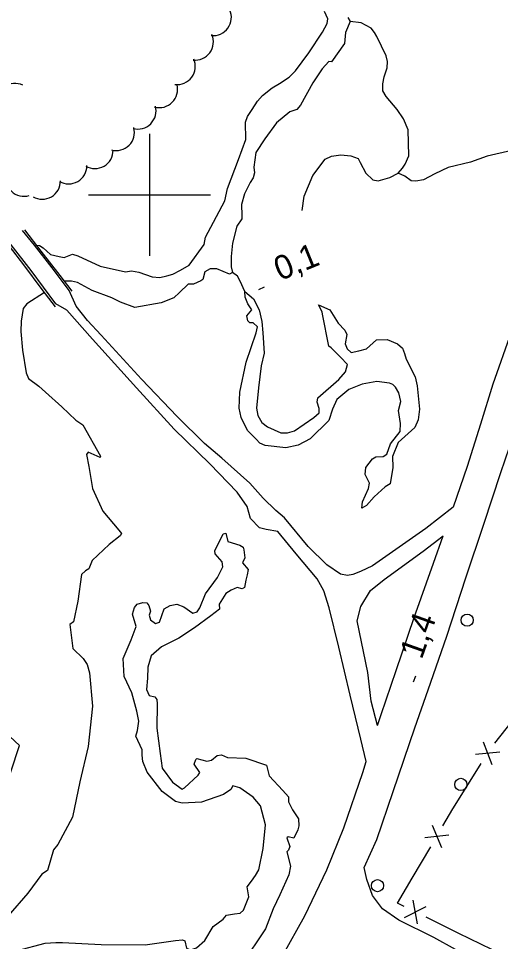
# Model space of a CAD drawing. Extents: x 362852 to 366875, y 5563573 to 5566479.
# Drawn here: x 363178.5 to 363257.7, y 5564877.4 to 5565029 of the extents above; entities that cross this region are included whole.
import ezdxf

# ---------------------------------------------------------------- set-up
doc = ezdxf.new("R2010")
doc.units = 0
for name, color, linetype in [('Niveau 21', 7, 'Continuous'), ('Niveau 26', 7, 'Continuous'), ('Niveau 3', 7, 'Continuous'), ('Niveau 36', 7, 'Continuous'), ('Niveau 37', 7, 'Continuous'), ('Niveau 4', 7, 'Continuous'), ('Niveau 44', 7, 'Continuous'), ('Niveau 61', 7, 'Continuous')]:
    doc.layers.add(name, color=color, linetype=linetype)

msp = doc.modelspace()

# ---------------------------------------------------------------- linework, layer by layer
at = {"layer": 'Niveau 21'}
for points in [[(363372.18, 5565057.69), (363361.37, 5565056.86), (363353.03, 5565055.6), (363345.44, 5565053.87), (363341.3, 5565052.93), (363331.73, 5565049.73), (363323.1, 5565046.35), (363314.99, 5565042.43), (363306.2, 5565037.55), (363298.33, 5565032.24), (363292.69, 5565027.74), (363288.13, 5565023.46), (363282, 5565017.44), (363277.14, 5565011.7), (363273.09, 5565006.11), (363268.51, 5564998.35), (363265.37, 5564991.56), (363261.94, 5564983.91), (363259.38, 5564977.44), (363256.38, 5564968.91), (363254.34, 5564962.36), (363252.17, 5564955.43), (363249.85, 5564948.72)], [(363235.23, 5564889.57), (363237.33, 5564894.18), (363240.03, 5564902.09), (363243.59, 5564912.52), (363245.79, 5564918.73), (363248.83, 5564927.56), (363251.95, 5564937.15), (363254.89, 5564945.97), (363257.71, 5564954.41), (363261.25, 5564964.85), (363262.65, 5564968.94), (363264.15, 5564973.34), (363266.65, 5564980.22), (363269.8, 5564986.99), (363272.24, 5564991.85), (363273.35, 5564994.06), (363277, 5565000.38), (363281.52, 5565006.79), (363283.56, 5565009.38), (363285.33, 5565011.62), (363291.51, 5565018.1), (363296.54, 5565023.16), (363302, 5565027.46), (363308.39, 5565031.6)], [(363249.85, 5564948.72), (363245.4, 5564945.21), (363242.67, 5564943.33), (363236.64, 5564939.13), (363234.66, 5564938.17), (363233.41, 5564937.71), (363232.49, 5564937.51), (363231.39, 5564937.74), (363229.15, 5564939.28), (363226.08, 5564942.3), (363222.15, 5564946.98), (363220.75, 5564948.21), (363218.65, 5564950.22), (363216.45, 5564952.66), (363211.89, 5564956.77), (363209.04, 5564959.17), (363204.56, 5564963.6), (363198.66, 5564969.77), (363192.06, 5564976.98), (363189.8, 5564979.4), (363187.96, 5564981.71), (363186.81, 5564984.28), (363184, 5564988.03), (363181.11, 5564991.77), (363179.16, 5564994.13)], [(363235.59, 5564906.98), (363234.69, 5564910.67), (363232.94, 5564917.89), (363231.1, 5564925.75), (363229.48, 5564932.21), (363228.65, 5564934.98), (363227.52, 5564936.98), (363224.08, 5564941.09), (363221.09, 5564944.75), (363219.16, 5564945.05), (363218.04, 5564945.34), (363216.61, 5564946.89), (363216.04, 5564948.85), (363214.4, 5564951.19), (363209.93, 5564955.84), (363204.06, 5564961.55), (363197.89, 5564968.32), (363190.66, 5564976.31), (363186.41, 5564981.06), (363184.62, 5564982.12), (363180.57, 5564987.58), (363176.88, 5564992.28)], [(363237.45, 5564912.88), (363236.42, 5564916.87), (363235.83, 5564921.58), (363234.11, 5564930.07), (363234.69, 5564932.44), (363236.29, 5564935.06), (363238.56, 5564936.87), (363244.95, 5564941.54), (363248.22, 5564944.04)], [(363237.45, 5564912.88), (363238.03, 5564914.7), (363240.53, 5564921.9), (363243.49, 5564930.63), (363246.64, 5564939.54), (363248.22, 5564944.04)], [(363178.37, 5564814.36), (363183.2, 5564821.26), (363185.41, 5564824.38), (363186.33, 5564825.68), (363188.95, 5564829.38), (363194.29, 5564836.07), (363200.53, 5564844.25), (363207.75, 5564854.22), (363212.87, 5564861.49), (363218.52, 5564869.7), (363221.84, 5564875.11), (363225.53, 5564881.64), (363229.14, 5564889.18), (363231.93, 5564896.12), (363235.02, 5564905.2), (363235.59, 5564906.98)], [(363326.71, 5564840.19), (363315.7, 5564841.25), (363310.05, 5564843.52), (363303.25, 5564846.91), (363296.85, 5564851.03), (363293.42, 5564852.83), (363286.86, 5564856.35), (363280.76, 5564860.38), (363274.34, 5564863.27), (363265.07, 5564867.95), (363257.39, 5564872.19), (363246.67, 5564878.08), (363240.95, 5564880.95), (363238.27, 5564882.79), (363236.6, 5564884.98), (363235.7, 5564887.6), (363235.23, 5564889.57)]]:
    msp.add_lwpolyline(points, dxfattribs=at)
at = {"layer": 'Niveau 26'}
for points in [[(363187.29, 5564984.17), (363185.32, 5564986.79), (363182.21, 5564990.75), (363179.5, 5564994.24)], [(363184.56, 5564981.62), (363182.36, 5564984.46), (363179.34, 5564988.52), (363176.99, 5564991.56)]]:
    msp.add_lwpolyline(points, dxfattribs=at)
at = {"layer": 'Niveau 3'}
for p, q in [((363217.93, 5564984.49), (363218.89, 5564984.88)), ((363243.38, 5564920.09), (363243.73, 5564921.07))]:
    msp.add_line(p, q, dxfattribs=at)
at = {"layer": 'Niveau 36'}
for centre in [(363252.16, 5564930.18), (363251.12, 5564903.23), (363237.44, 5564886.61)]:
    msp.add_circle(centre, 1, dxfattribs=at)
at = {"layer": 'Niveau 37'}
for p, q in [((363256.71, 5564909.98), (363260.42, 5564914.69)), ((363254.79, 5564910.23), (363256.24, 5564906.51)), ((363253.52, 5564908.2), (363257.51, 5564908.55)), ((363251.3, 5564901.58), (363254.46, 5564906.68)), ((363246.42, 5564896.56), (363247.96, 5564892.87)), ((363245.2, 5564894.49), (363249.18, 5564894.93)), ((363243.14, 5564887.82), (363246.18, 5564892.99)), ((363244.02, 5564880.32), (363243.28, 5564884.25)), ((363241.87, 5564881.38), (363245.43, 5564883.2)), ((363250.82, 5564878.76), (363245.44, 5564881.41)), ((363256.21, 5564876.11), (363250.82, 5564878.76))]:
    msp.add_line(p, q, dxfattribs=at)
for points in [[(363248.2, 5564896.44), (363249.84, 5564899.23), (363251.3, 5564901.58)], [(363241.85, 5564883.17), (363240.73, 5564883.72), (363243.14, 5564887.82)]]:
    msp.add_lwpolyline(points, dxfattribs=at)
at = {"layer": 'Niveau 4'}
msp.add_line((363215.72, 5564983.2), (363215.65, 5564984.12), dxfattribs=at)
for points in [[(363181.45, 5564991.73), (363181.94, 5564991.67), (363182.54, 5564991.29), (363183.74, 5564990.23), (363185.14, 5564989.88), (363185.96, 5564989.72), (363187.37, 5564990.25), (363188.24, 5564989.98), (363191.89, 5564988.31), (363196.06, 5564987.36), (363197.06, 5564987.53), (363198.27, 5564987.34), (363200.42, 5564986.55), (363201.71, 5564986.46), (363202.87, 5564986.7), (363203.82, 5564986.97), (363205.11, 5564987.64), (363206.52, 5564988.48), (363209, 5564991.85), (363209.18, 5564993.05), (363210.07, 5564994.68), (363212.38, 5564999.04), (363212.8, 5565001.04), (363214.62, 5565005.83), (363215.82, 5565009.1), (363215.75, 5565011.96), (363216.07, 5565012.84), (363216.85, 5565013.99), (363217.72, 5565015.36), (363218.56, 5565016.34), (363220.12, 5565017.56), (363221.34, 5565018.26), (363222.96, 5565019.32), (363223.97, 5565020.36), (363226.19, 5565023.31), (363228.41, 5565026.69), (363229.18, 5565028.14), (363229.31, 5565028.89), (363228.74, 5565030.09)], [(363232.59, 5565029.14), (363232.94, 5565028.46), (363232.2, 5565026.64), (363232, 5565024.87), (363229.88, 5565021.84), (363229.47, 5565021.92), (363228.35, 5565020.7), (363226.8, 5565018.41), (363224.82, 5565014.75)], [(363225.07, 5564997.43), (363225.41, 5564999.77), (363226.8, 5565003.18), (363228.85, 5565005.84), (363229.89, 5565006.34), (363231.44, 5565006.55), (363233.06, 5565006.42), (363234.25, 5565005.98), (363234.6, 5565005.3), (363235.52, 5565003.56), (363236.67, 5565002.47), (363237.54, 5565002.33), (363239.45, 5565002.88), (363240.85, 5565003.59), (363241.57, 5565004.4), (363242, 5565005.02), (363242.61, 5565006.41), (363242.46, 5565010.67), (363241.69, 5565012.49), (363240.68, 5565014.01), (363238.84, 5565016.13), (363238.31, 5565017.1), (363238.33, 5565018.24), (363238.54, 5565019.4), (363239.05, 5565020.87), (363239.07, 5565021.88), (363238.85, 5565022.85), (363237.34, 5565025.99), (363236.94, 5565026.64), (363236.39, 5565027.35), (363234.76, 5565028.24), (363232.94, 5565028.46)], [(363224.82, 5565014.75), (363224.19, 5565013.99), (363223.03, 5565013.63), (363220.83, 5565011.83), (363218.92, 5565009.2), (363217.47, 5565006.96), (363217.11, 5565004.55), (363217.25, 5565003.6), (363217.02, 5565002.81), (363216.53, 5565002.04), (363215.62, 5565000.15), (363215.09, 5564998.42), (363215.16, 5564996.63), (363215.14, 5564996.06), (363214.34, 5564994.84), (363213.61, 5564992.08), (363213.41, 5564989.87), (363213.43, 5564988.18), (363213.63, 5564987.25), (363213.12, 5564986.98), (363211.05, 5564987.87), (363209.98, 5564987.86), (363209.07, 5564987.35), (363208.78, 5564986.1), (363208.42, 5564985.89), (363207.22, 5564985.32), (363206.34, 5564985.33), (363204.9, 5564983.97), (363204.01, 5564983.09), (363201.9, 5564982.27), (363197.57, 5564981.52), (363195.26, 5564982.38), (363193.83, 5564983.09), (363190.56, 5564984.3), (363188.18, 5564985.62), (363187.21, 5564985.84), (363186.02, 5564985.85)], [(363264.12, 5565006.75), (363261.21, 5565007.33), (363259.5, 5565007.29), (363255.43, 5565006.37), (363252.7, 5565005.38), (363249.06, 5565004.48), (363246.86, 5565003.43), (363245.01, 5565002.46), (363243.72, 5565002.24), (363242.95, 5565002.29), (363241.93, 5565003.06), (363240.85, 5565003.59)], [(363215.65, 5564984.12), (363214.89, 5564985.84), (363214.45, 5564986.63), (363213.63, 5564987.25)], [(363215.65, 5564984.12), (363217.08, 5564982.96), (363218.03, 5564981.15), (363218.47, 5564979.2), (363218.61, 5564977.38), (363218.83, 5564974.02), (363218.32, 5564971.92), (363217.88, 5564968.34), (363217.58, 5564965.01), (363217.79, 5564963.78), (363218.46, 5564962.62), (363219.38, 5564961.94), (363221.55, 5564960.96), (363222.69, 5564960.94), (363223.8, 5564961.28), (363226.98, 5564963.43), (363227.89, 5564964.25), (363227.85, 5564964.93), (363227.54, 5564965.99), (363227.63, 5564966.66), (363231.08, 5564969.67), (363232.17, 5564970.95), (363232.54, 5564972.17), (363231.39, 5564973.34), (363229.81, 5564974.87), (363229.44, 5564975.16), (363228.41, 5564980.44), (363228.33, 5564980.78), (363227.78, 5564981.94), (363229.62, 5564981.14), (363230.98, 5564978.95), (363232.1, 5564977.78), (363232.39, 5564977.09), (363232.16, 5564975.55), (363232.44, 5564974.72), (363233.13, 5564974.13), (363234.4, 5564974.41), (363235.64, 5564974.74), (363237.29, 5564976.19), (363239.01, 5564976.28), (363240.75, 5564975.57), (363241.56, 5564974.84), (363241.87, 5564973.97), (363242.14, 5564973.01), (363243.61, 5564970.11), (363243.98, 5564968.64), (363244.33, 5564964.82), (363244.13, 5564963.05), (363243.58, 5564961.81), (363240.85, 5564959.35), (363239.89, 5564957.08), (363239.98, 5564955.23), (363239.52, 5564952.59), (363238.68, 5564952.05), (363236.91, 5564950.43), (363235.62, 5564949.01), (363234.87, 5564948.56), (363234.99, 5564949.62), (363235.96, 5564951.79), (363236.15, 5564952.68), (363235.44, 5564954.08), (363235.51, 5564955.24), (363236.62, 5564956.65), (363237.16, 5564957), (363238.39, 5564957.08), (363238.98, 5564957.45), (363239.59, 5564959.15), (363241.15, 5564961.17), (363241.24, 5564962.46), (363240.91, 5564964.58), (363241.29, 5564966.06), (363240.95, 5564967.49), (363240.41, 5564968.46), (363239.98, 5564968.9), (363239.44, 5564969.12), (363237.33, 5564969.36), (363234.94, 5564968.93), (363232.73, 5564968.06), (363230.75, 5564966.4), (363230.03, 5564964.84), (363229.44, 5564962.95), (363226.36, 5564959.97), (363224.42, 5564958.9), (363222.39, 5564958.49), (363218.97, 5564958.87), (363218.13, 5564959.22), (363217.53, 5564959.9), (363216.12, 5564961.32), (363215.04, 5564963.44), (363214.7, 5564965), (363214.85, 5564967.64), (363215.87, 5564972.52), (363217.54, 5564977.37), (363217.76, 5564978.34), (363217.05, 5564978.99), (363216.48, 5564979), (363216.16, 5564979.31), (363215.99, 5564980.17), (363216.78, 5564981.13), (363216.17, 5564982.13), (363215.72, 5564983.2)], [(363182.75, 5564983.96), (363179.85, 5564982.13), (363179.23, 5564981.36), (363178.91, 5564979.28), (363178.88, 5564977.57), (363179.17, 5564974.49), (363179.73, 5564970.77), (363180.11, 5564969.86), (363181.84, 5564968.58), (363182.94, 5564967.59), (363185.59, 5564965.19), (363187.88, 5564963.01), (363189.03, 5564962.23), (363191.93, 5564957.11), (363191.89, 5564956.9), (363189.95, 5564957.78), (363189.67, 5564957.41), (363190.06, 5564955.44), (363190.65, 5564951.79), (363192.33, 5564948.1), (363194.97, 5564944.94), (363195.38, 5564944.42), (363195.17, 5564944.01), (363193.37, 5564942.63), (363190.59, 5564939.96), (363190.04, 5564938.59), (363189.47, 5564938.29), (363188.84, 5564937.71), (363188.23, 5564933.31), (363187.52, 5564929.93), (363186.89, 5564929.48), (363187.41, 5564925.55), (363189.12, 5564923.88), (363189.78, 5564922.9), (363190.16, 5564921.56), (363190.65, 5564916.05), (363189.9, 5564909.45), (363188.56, 5564903.67), (363187.37, 5564897.83), (363184.97, 5564893.37), (363184.21, 5564892.49), (363183.24, 5564889.12), (363182.31, 5564888.49), (363180.03, 5564885.39), (363176.77, 5564881.64)], [(363217.93, 5564889.23), (363218.68, 5564892.69), (363219.03, 5564896.57), (363218.23, 5564899.69), (363217.05, 5564901.14), (363214.84, 5564902.66), (363213.7, 5564903), (363213.37, 5564902.42), (363212.15, 5564901.6), (363208.54, 5564900.33), (363205.36, 5564900.13), (363204.29, 5564900.43), (363202.08, 5564902.08), (363199.62, 5564905.26), (363198.9, 5564906.97), (363198.77, 5564908.04), (363198.77, 5564908.92), (363197.78, 5564911.14), (363198.02, 5564912.06), (363198.25, 5564913.6), (363197.94, 5564915.23), (363197.1, 5564918.27), (363195.85, 5564920.95), (363195.69, 5564923.9), (363196.98, 5564926.95), (363197.82, 5564929.13), (363197.21, 5564931.19), (363197.51, 5564932.26), (363197.96, 5564932.83), (363198.92, 5564933.1), (363199.58, 5564933.01), (363199.89, 5564932.57), (363200.14, 5564931.67), (363199.97, 5564931.03), (363200.18, 5564930.24), (363201, 5564929.64), (363201.66, 5564929.86), (363202.43, 5564932.07), (363203.4, 5564932.6), (363204.5, 5564932.81), (363205.62, 5564932.4), (363207.13, 5564931.34), (363207.85, 5564931.58), (363208.28, 5564932.2), (363209.18, 5564934.52), (363211.18, 5564937.2), (363212.02, 5564938.94), (363211.92, 5564939.77), (363210.81, 5564941.07), (363210.71, 5564941.59), (363212.12, 5564944.38), (363212.51, 5564944.48), (363212.84, 5564943.11), (363214.85, 5564942.51), (363215.37, 5564942.17), (363215.5, 5564941.72), (363215.67, 5564940.41), (363215.26, 5564939.6), (363216.22, 5564938.5), (363216.03, 5564937.61), (363215.82, 5564936.76), (363215.58, 5564935.53), (363215.23, 5564935.32), (363214.39, 5564935.53), (363213.43, 5564935.13), (363212.51, 5564934.54), (363211.46, 5564932.84), (363211.51, 5564931.98), (363210.09, 5564930.88), (363207.39, 5564928.93), (363204.84, 5564927.23), (363201.99, 5564925.79), (363200.28, 5564924.32), (363199.74, 5564922.46), (363199.68, 5564920.67), (363199.53, 5564918.79), (363199.93, 5564917.83), (363200.85, 5564917.58), (363201.21, 5564917.17), (363201.27, 5564916.44), (363201.18, 5564912.45), (363201.74, 5564908.28), (363202.1, 5564905.92), (363203.77, 5564903.61), (363205.38, 5564902.46), (363205.73, 5564902.67), (363208, 5564904.75), (363208.26, 5564905.18), (363207.36, 5564906.56), (363207.62, 5564907.3), (363207.79, 5564907.49), (363209.42, 5564907.05), (363210.16, 5564907.23), (363211.09, 5564908), (363211.8, 5564908.11), (363212.81, 5564907.65), (363215.81, 5564907.53), (363219.19, 5564906.37), (363219.67, 5564904.63), (363221.87, 5564902.22), (363222.82, 5564901.17)], [(363175.82, 5564900.96), (363178.65, 5564909.63), (363177.08, 5564911.11)], [(363222.82, 5564901.17), (363222.84, 5564900.37), (363223.46, 5564899.05), (363224.45, 5564897.59), (363224.55, 5564896.44), (363224.38, 5564895.8), (363223.72, 5564894.39), (363222.8, 5564894.63), (363222.56, 5564894.47), (363223.03, 5564893.03), (363222.84, 5564892.45), (363222.58, 5564892.15), (363223.18, 5564889.83), (363222.86, 5564888.41), (363221.42, 5564885.11), (363220.31, 5564882.82), (363219.05, 5564879.53), (363215.14, 5564873.74)], [(363178.34, 5564875.95), (363182.86, 5564877.16), (363184.64, 5564877.27), (363185.7, 5564877.28), (363192.06, 5564876.93), (363199.3, 5564876.89), (363204.28, 5564877.6), (363205.43, 5564877.71), (363205.81, 5564877.55), (363206.07, 5564876.34), (363206.75, 5564876.06), (363207.74, 5564876.41), (363209.06, 5564877.6), (363210.48, 5564879.89), (363212.1, 5564881.13), (363212.66, 5564881.74), (363213.94, 5564881.97), (363214.89, 5564882.12), (363215.44, 5564882.6), (363216.34, 5564884.8), (363216.03, 5564886.43), (363216.77, 5564887.36), (363217.4, 5564888.26), (363217.93, 5564889.23)]]:
    msp.add_lwpolyline(points, dxfattribs=at)
at = {"layer": 'Niveau 44'}
for centre, start, end in [((363210.45, 5565029.14), 264.2219, 24.1999), ((363207.5, 5565025.12), 263.4399, 23.4178), ((363204.52, 5565021.11), 263.4399, 23.4178), ((363177.86, 5565015.31), 63.6472, 183.6251), ((363201.62, 5565017.32), 254.876, 14.8539), ((363198.08, 5565013.8), 254.876, 14.8539), ((363194.53, 5565010.27), 254.876, 14.8539), ((363191.03, 5565007.32), 240.2054, 0.1834), ((363186.71, 5565004.8), 240.2054, 0.1834), ((363179.39, 5565002.78), 166.4569, 286.4349), ((363182.38, 5565002.29), 240.2054, 0.1834)]:
    msp.add_arc(centre, 3, start, end, dxfattribs=at)
at = {"layer": 'Niveau 61'}
for p, q in [((363200, 5565010), (363200, 5564990)), ((363190, 5565000), (363210, 5565000))]:
    msp.add_line(p, q, dxfattribs=at)

# ---------------------------------------------------------------- texts
at = {"layer": 'Niveau 3'}
for s, rotation, p in [('0,1  ', 22.09, (363221.44, 5564985.85)), ('1,4  ', 70.4684, (363244.7, 5564923.62))]:
    msp.add_text(s, height=3.93, rotation=rotation, dxfattribs=at).set_placement(p)

doc.saveas('drawing.dxf')
